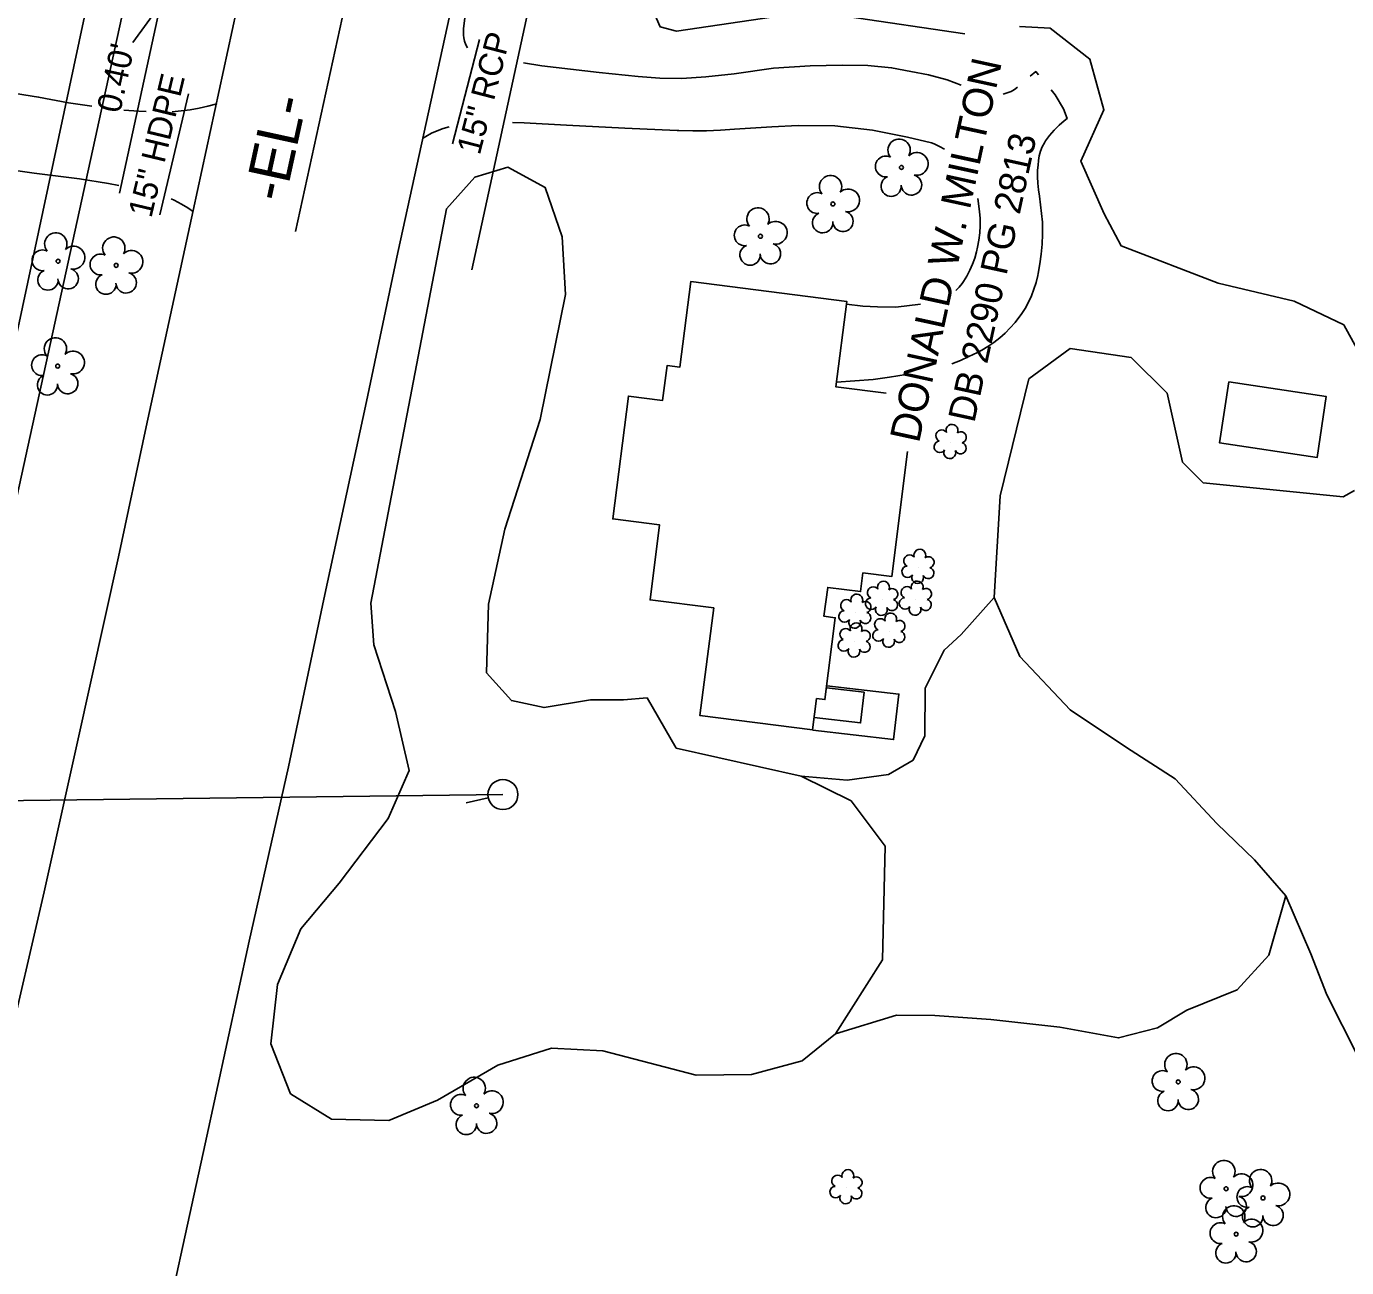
# Model space of a CAD drawing. Extents: x 1611576 to 1617186, y 899279 to 905462.
# Drawn here: x 1616512.4 to 1616732.1, y 901153.2 to 901359.7 of the extents above; entities that cross this region are included whole.
import ezdxf

# ---------------------------------------------------------------- set-up
doc = ezdxf.new("R2010")
doc.units = 0
for name, color, linetype in [('Default', 7, 'Continuous'), ('Exist Building', 7, 'Continuous'), ('Exist Horizontal Alignment', 7, 'Continuous'), ('Exist Horizontal Alignment Direction Label', 7, 'Continuous'), ('Exist Other Culture Area Outline', 7, 'Continuous'), ('Exist Property Deed Book Text', 7, 'Continuous'), ('Exist Property Line Leader', 7, 'Continuous'), ('Exist Property Line Text', 7, 'Continuous'), ('Exist Property Owner Text', 7, 'Continuous'), ('Exist Right of Way Line', 7, 'Continuous'), ('Exist Roads EOP', 7, 'Continuous'), ('Exist Roads Soil', 7, 'Continuous'), ('Exist Structure Minor Pipes HDPE 15 Inch', 7, 'Continuous'), ('Exist Structure Minor Pipes HDPE 15 Inch Text', 7, 'Continuous'), ('Exist Structure Minor Pipes RCP 15 Inch', 7, 'Continuous'), ('Exist Structure Minor Pipes RCP 15 Inch Text', 7, 'Continuous'), ('Exist Vegetation Hedge Row', 7, 'Continuous'), ('Exist Vegetation Shrub CELL', 7, 'Continuous'), ('Exist Vegetation Tree CELL', 7, 'Continuous'), ('Exist Vegetation Woods Line', 7, 'Continuous'), ('Prop 6 In Gas Line (B2)', 7, 'Continuous'), ('Prop OH Pow Lines', 7, 'Continuous'), ('Prop OH Pow Tel CATV Lines', 7, 'Continuous')]:
    doc.layers.add(name, color=color, linetype=linetype)

msp = doc.modelspace()

# ---------------------------------------------------------------- linework, layer by layer
at = {"layer": 'Default'}
msp.add_line((1616589.28, 901231.39), (1616585.62, 901230.55), dxfattribs=at)
msp.add_circle((1616591.71, 901231.94), 2.5, dxfattribs=at)
at = {"layer": 'Exist Building'}
msp.add_lwpolyline([(1616659.05, 901289.01), (1616656.41, 901268.21), (1616651.62, 901268.82), (1616651.23, 901265.71), (1616645.75, 901266.41), (1616645.13, 901261.6), (1616647.02, 901261.36), (1616645.28, 901247.73), (1616643.89, 901247.9), (1616643.23, 901242.69), (1616624.5, 901245.07), (1616626.78, 901262.99), (1616616.19, 901264.33), (1616617.78, 901276.79), (1616609.99, 901277.78), (1616612.59, 901298.23), (1616618.28, 901297.51), (1616619.02, 901303.31), (1616621.16, 901303.04), (1616622.97, 901317.27), (1616648.92, 901313.97), (1616647.11, 901299.76), (1616655.48, 901298.7)], dxfattribs=at)
msp.add_lwpolyline([(1616712.49, 901300.59), (1616728.7, 901298.15), (1616727.17, 901288), (1616710.96, 901290.44)], close=True, dxfattribs=at)
at = {"layer": 'Exist Horizontal Alignment'}
msp.add_line((1616557.22, 901325.62), (1616574.73, 901406.06), dxfattribs=at)
at = {"layer": 'Exist Other Culture Area Outline'}
for points in [[(1616645.58, 901250.04), (1616657.59, 901248.64), (1616656.71, 901241.09), (1616643.29, 901242.65)], [(1616645.54, 901249.7), (1616651.81, 901248.97), (1616651.21, 901243.87), (1616643.49, 901244.78)]]:
    msp.add_lwpolyline(points, dxfattribs=at)
at = {"layer": 'Exist Property Line Leader'}
msp.add_line((1616534.45, 901362.96), (1616530.14, 901357.04), dxfattribs=at)
at = {"layer": 'Exist Right of Way Line'}
for p, q in [((1616527.91, 901332), (1616545.42, 901412.44)), ((1616586.53, 901319.24), (1616604.05, 901399.68))]:
    msp.add_line(p, q, dxfattribs=at)
at = {"layer": 'Exist Roads EOP'}
for points in [[(1616540.19, 901329.11), (1616548.81, 901369.07), (1616557.77, 901410.37), (1616567.02, 901453.27), (1616575.93, 901495.52), (1616585.07, 901537.99), (1616593.68, 901579.55), (1616600.7, 901615.07)], [(1616637.67, 901615.79), (1616627.7, 901573.43), (1616618.84, 901530.91), (1616609.97, 901489.21), (1616601.04, 901446.38), (1616592.15, 901403.91), (1616582.89, 901361.63), (1616574.25, 901322.14)], [(1616508.56, 901186.1), (1616509, 901188.14), (1616515.39, 901215.77), (1616520.9, 901240.73), (1616527.75, 901271.5), (1616532.38, 901293.11), (1616540.19, 901329.11)], [(1616574.25, 901322.14), (1616569.01, 901297.34), (1616561.91, 901264.45), (1616556.05, 901236.56), (1616549.5, 901207.53), (1616542.18, 901173.84), (1616533.69, 901135.03)]]:
    msp.add_lwpolyline(points, dxfattribs=at)
at = {"layer": 'Exist Roads Soil'}
for points in [[(1616585.81, 901356.14), (1616585.53, 901356.68), (1616585.33, 901357.25), (1616585.19, 901357.84), (1616585.15, 901358.27), (1616585.16, 901359.39), (1616585.77, 901364.24), (1616586.93, 901371.54), (1616587.46, 901376.46), (1616587.58, 901382.96)], [(1616523.33, 901346.48), (1616519.44, 901347.01), (1616514.46, 901347.97), (1616509.21, 901348.79), (1616505.25, 901349.23), (1616499.66, 901349.68), (1616493.34, 901350.26), (1616486.34, 901351.16), (1616473.14, 901353.09), (1616460.08, 901355.19), (1616448.14, 901357.11), (1616436.59, 901359.1), (1616422.94, 901361.95)], [(1616667.94, 901349.96), (1616665.63, 901350.82), (1616662.52, 901351.67), (1616659.57, 901352.23), (1616656.37, 901352.84), (1616652.44, 901353.23), (1616648.15, 901353.29), (1616642.85, 901353.15), (1616636.73, 901352.76), (1616630.18, 901351.84), (1616625.46, 901351.32), (1616621.46, 901351.05), (1616617.81, 901351.12), (1616614.23, 901351.4), (1616607.71, 901352.04), (1616598.21, 901353.19), (1616595.11, 901353.67)], [(1616680.82, 901351.69), (1616680.36, 901352.21), (1616679.45, 901351.44)], [(1616666.38, 901303.62), (1616667.83, 901304.17), (1616669.26, 901304.79), (1616670.66, 901305.49), (1616671.37, 901305.87), (1616672.41, 901306.48), (1616673.42, 901307.16), (1616674.37, 901307.9), (1616675.28, 901308.7), (1616676.13, 901309.56), (1616676.93, 901310.47), (1616677.24, 901310.87), (1616677.94, 901311.82), (1616678.58, 901312.81), (1616679.15, 901313.84), (1616679.65, 901314.91), (1616680.07, 901316.01), (1616680.42, 901317.14), (1616680.69, 901318.28), (1616680.76, 901318.61), (1616681.06, 901320.23), (1616681.28, 901321.86), (1616681.43, 901323.5), (1616681.5, 901325.14), (1616681.49, 901326.78), (1616681.47, 901327.18), (1616680.97, 901331.49), (1616680.8, 901332.56), (1616680.69, 901333.63), (1616680.65, 901334.72), (1616680.68, 901335.8), (1616680.75, 901336.63), (1616680.81, 901337.41), (1616680.94, 901338.19), (1616681.15, 901338.95), (1616681.44, 901339.68), (1616681.8, 901340.38), (1616681.99, 901340.69), (1616682.68, 901341.6), (1616683.43, 901342.46), (1616684.24, 901343.27), (1616685.11, 901344.03), (1616685.62, 901344.42), (1616685.01, 901346.02), (1616683.61, 901348.34), (1616682.94, 901349.2)], [(1616677.32, 901349.64), (1616676.85, 901349.25), (1616676.25, 901348.91), (1616675.62, 901348.65), (1616674.96, 901348.46)], [(1616544.09, 901346.83), (1616542.63, 901346.43), (1616541.15, 901346.1), (1616539.66, 901345.84), (1616538.16, 901345.66), (1616536.66, 901345.54)], [(1616532.37, 901345.58), (1616531.12, 901345.63), (1616528.64, 901345.8)], [(1616582.79, 901343.03), (1616581.77, 901342.74), (1616580.78, 901342.38), (1616579.81, 901341.94), (1616578.88, 901341.43), (1616578.34, 901341.09)], [(1616665.19, 901339.29), (1616664.34, 901339.77), (1616663.46, 901340.18), (1616663.02, 901340.35), (1616659, 901341.29), (1616653.23, 901342.44), (1616646.92, 901343.16), (1616640.85, 901343.26), (1616636.45, 901343.04), (1616630.24, 901342.64), (1616627.93, 901342.46), (1616625.61, 901342.37), (1616623.29, 901342.36), (1616620.97, 901342.42), (1616620.73, 901342.43), (1616612, 901342.79), (1616602.3, 901343.29), (1616595.24, 901343.67), (1616593.32, 901343.74)], [(1616460.38, 901326.31), (1616464.07, 901327.91), (1616467.97, 901329.54), (1616471.15, 901330.85), (1616474.63, 901332.24), (1616478.05, 901333.56), (1616481.89, 901334.93), (1616484.93, 901335.73), (1616488.23, 901336.48), (1616491.34, 901336.98), (1616492.83, 901337.1), (1616496.3, 901337.13), (1616499.77, 901336.95), (1616503.08, 901336.62), (1616507.42, 901336.19), (1616513.71, 901335.32), (1616521.24, 901334.36), (1616526.1, 901333.58), (1616527.83, 901333.25)], [(1616536.51, 901331.02), (1616537, 901330.81), (1616538.22, 901330.15), (1616539.31, 901329.52), (1616540.21, 901328.87)], [(1616667.07, 901315.79), (1616667.62, 901316.35), (1616668.11, 901316.97), (1616668.32, 901317.28), (1616668.9, 901318.2), (1616669.42, 901319.15), (1616669.86, 901320.15), (1616670.22, 901321.17), (1616670.51, 901322.22), (1616670.68, 901323.01), (1616670.91, 901324.18), (1616671.06, 901325.36), (1616671.13, 901326.55), (1616671.12, 901327.75), (1616671.03, 901328.94), (1616670.75, 901331.12)], [(1616648.86, 901313.52), (1616651.6, 901313.19), (1616654.06, 901313.07), (1616657.1, 901313.04), (1616661.2, 901313.5)], [(1616647.21, 901300.53), (1616653.31, 901301), (1616656.05, 901301.37), (1616658.79, 901301.82)]]:
    msp.add_lwpolyline(points, dxfattribs=at)
at = {"layer": 'Exist Structure Minor Pipes HDPE 15 Inch'}
msp.add_line((1616539.41, 901348.52), (1616534.61, 901328.4), dxfattribs=at)
at = {"layer": 'Exist Structure Minor Pipes RCP 15 Inch'}
msp.add_line((1616583.3, 901340.18), (1616587.79, 901357.52), dxfattribs=at)
msp.add_line((1616583.3, 901340.18), (1616587.79, 901357.52), dxfattribs=at)
at = {"layer": 'Exist Vegetation Hedge Row'}
for points in [[(1616641.34, 901234.99), (1616648.97, 901234.35), (1616655.87, 901235.25), (1616659.97, 901237.67), (1616661.9, 901241.71), (1616661.94, 901249.63), (1616665.15, 901255.97), (1616667.98, 901258.55), (1616673.47, 901264.74)], [(1616722, 901215.09), (1616719.16, 901205.22), (1616713.86, 901199.46), (1616705.48, 901196.06), (1616700.62, 901193.14), (1616694.15, 901191.44), (1616684.38, 901193.24), (1616672.92, 901194.54), (1616663.58, 901195.17), (1616657.19, 901195.24), (1616647.03, 901192.15)]]:
    msp.add_lwpolyline(points, dxfattribs=at)
at = {"layer": 'Exist Vegetation Shrub CELL'}
for p, q in [((1616666.2, 901290.49), (1616666.2, 901290.49)), ((1616660.85, 901269.71), (1616660.85, 901269.71)), ((1616654.8, 901264.4), (1616654.8, 901264.4)), ((1616660.41, 901264.43), (1616660.41, 901264.43)), ((1616650.36, 901262.27), (1616650.36, 901262.27)), ((1616656.01, 901259.1), (1616656.01, 901259.1)), ((1616650.23, 901257.46), (1616650.23, 901257.46)), ((1616648.87, 901166.52), (1616648.87, 901166.52))]:
    msp.add_line(p, q, dxfattribs=at)
for centre, radius, start, end in [((1616664.72, 901291.62), 0.968, 35.8908, 245.4216), ((1616666.43, 901292.53), 0.99, 334.8391, 200.4717), ((1616667.87, 901291.36), 0.929, 284.4567, 126.0861), ((1616664.4, 901289.78), 0.955, 95.1099, 327.9534), ((1616667.84, 901289.56), 0.937, 204.9913, 73.4601), ((1616666.07, 901288.8), 0.984, 151.2797, 21.387), ((1616661.08, 901271.76), 0.99, 334.8391, 200.4717), ((1616659.05, 901269.01), 0.955, 95.1099, 327.9534), ((1616659.37, 901270.84), 0.968, 35.8908, 245.4216), ((1616662.49, 901268.79), 0.937, 204.9913, 73.4601), ((1616662.52, 901270.58), 0.929, 284.4567, 126.0861), ((1616660.72, 901268.03), 0.984, 151.2797, 21.387), ((1616650.59, 901264.31), 0.99, 334.8391, 200.4717), ((1616653.32, 901265.53), 0.968, 35.8908, 245.4216), ((1616655.03, 901266.44), 0.99, 334.8391, 200.4717), ((1616656.48, 901265.27), 0.929, 284.4567, 126.0861), ((1616658.93, 901265.56), 0.968, 35.8908, 245.4216), ((1616660.64, 901266.47), 0.99, 334.8391, 200.4717), ((1616662.08, 901265.3), 0.929, 284.4567, 126.0861), ((1616648.88, 901263.4), 0.968, 35.8908, 245.4216), ((1616652.03, 901263.14), 0.929, 284.4567, 126.0861), ((1616653, 901263.69), 0.955, 95.1099, 327.9534), ((1616654.68, 901262.71), 0.984, 151.2797, 21.387), ((1616656.44, 901263.47), 0.937, 204.9913, 73.4601), ((1616658.61, 901263.72), 0.955, 95.1099, 327.9534), ((1616660.28, 901262.75), 0.984, 151.2797, 21.387), ((1616662.05, 901263.5), 0.937, 204.9913, 73.4601), ((1616648.56, 901261.57), 0.955, 95.1099, 327.9534), ((1616650.23, 901260.59), 0.984, 151.2797, 21.387), ((1616652, 901261.34), 0.937, 204.9913, 73.4601), ((1616654.52, 901260.23), 0.968, 35.8908, 245.4216), ((1616656.24, 901261.14), 0.99, 334.8391, 200.4717), ((1616657.68, 901259.97), 0.929, 284.4567, 126.0861), ((1616648.75, 901258.59), 0.968, 35.8908, 245.4216), ((1616650.46, 901259.5), 0.99, 334.8391, 200.4717), ((1616651.91, 901258.33), 0.929, 284.4567, 126.0861), ((1616654.21, 901258.4), 0.955, 95.1099, 327.9534), ((1616657.64, 901258.17), 0.937, 204.9913, 73.4601), ((1616648.43, 901256.75), 0.955, 95.1099, 327.9534), ((1616651.87, 901256.53), 0.937, 204.9913, 73.4601), ((1616655.88, 901257.42), 0.984, 151.2797, 21.387), ((1616650.11, 901255.78), 0.984, 151.2797, 21.387), ((1616649.1, 901168.56), 0.99, 334.8391, 200.4717), ((1616647.07, 901165.81), 0.955, 95.1099, 327.9534), ((1616647.39, 901167.65), 0.968, 35.8908, 245.4216), ((1616650.51, 901165.59), 0.937, 204.9913, 73.4601), ((1616650.54, 901167.39), 0.929, 284.4567, 126.0861), ((1616648.74, 901164.84), 0.984, 151.2797, 21.387)]:
    msp.add_arc(centre, radius, start, end, dxfattribs=at)
at = {"layer": 'Exist Vegetation Tree CELL'}
for p, q in [((1616658.02, 901336.26), (1616658.02, 901336.26)), ((1616646.61, 901330.19), (1616646.61, 901330.19)), ((1616634.55, 901324.81), (1616634.55, 901324.81)), ((1616517.7, 901320.66), (1616517.7, 901320.66)), ((1616527.36, 901319.97), (1616527.36, 901319.97)), ((1616517.63, 901303.21), (1616517.63, 901303.21)), ((1616704.07, 901184.14), (1616704.07, 901184.14)), ((1616587.32, 901180.17), (1616587.32, 901180.17)), ((1616712.04, 901166.36), (1616712.04, 901166.36)), ((1616718.18, 901164.83), (1616718.18, 901164.83)), ((1616713.71, 901158.81), (1616713.71, 901158.81))]:
    msp.add_line(p, q, dxfattribs=at)
for centre in [(1616658.02, 901336.26), (1616646.61, 901330.19), (1616634.55, 901324.81), (1616517.7, 901320.66), (1616527.36, 901319.97), (1616517.63, 901303.21), (1616704.07, 901184.14), (1616587.32, 901180.17), (1616712.04, 901166.36), (1616718.18, 901164.83), (1616713.71, 901158.81)]:
    msp.add_circle(centre, 0.326, dxfattribs=at)
for centre, radius, start, end in [((1616657.63, 901339.14), 1.86, 330.1651, 219.7134), ((1616655.41, 901336.42), 1.73, 62.6636, 279.3457), ((1616660.57, 901336.85), 1.9, 257.1011, 134.1999), ((1616646.23, 901333.06), 1.86, 330.1651, 219.7134), ((1616656.31, 901333.14), 1.69, 111.5671, 6.231), ((1616659.69, 901333.36), 1.7, 181.2822, 74.56), ((1616644.01, 901330.34), 1.73, 62.6636, 279.3457), ((1616649.16, 901330.78), 1.9, 257.1011, 134.1999), ((1616634.16, 901327.69), 1.86, 330.1651, 219.7134), ((1616637.1, 901325.4), 1.9, 257.1011, 134.1999), ((1616644.91, 901327.07), 1.69, 111.5671, 6.231), ((1616648.28, 901327.29), 1.7, 181.2822, 74.56), ((1616517.32, 901323.53), 1.86, 330.1651, 219.7134), ((1616526.97, 901322.84), 1.86, 330.1651, 219.7134), ((1616631.94, 901324.97), 1.73, 62.6636, 279.3457), ((1616515.1, 901320.81), 1.73, 62.6636, 279.3457), ((1616520.25, 901321.25), 1.9, 257.1011, 134.1999), ((1616529.9, 901320.56), 1.9, 257.1011, 134.1999), ((1616632.84, 901321.69), 1.69, 111.5671, 6.231), ((1616636.22, 901321.91), 1.7, 181.2822, 74.56), ((1616524.75, 901320.12), 1.73, 62.6636, 279.3457), ((1616516, 901317.54), 1.69, 111.5671, 6.231), ((1616519.37, 901317.76), 1.7, 181.2822, 74.56), ((1616525.65, 901316.85), 1.69, 111.5671, 6.231), ((1616529.03, 901317.07), 1.7, 181.2822, 74.56), ((1616517.25, 901306.08), 1.86, 330.1651, 219.7134), ((1616515.02, 901303.37), 1.73, 62.6636, 279.3457), ((1616520.18, 901303.8), 1.9, 257.1011, 134.1999), ((1616515.93, 901300.09), 1.69, 111.5671, 6.231), ((1616519.3, 901300.31), 1.7, 181.2822, 74.56), ((1616703.69, 901187.01), 1.86, 330.1651, 219.7134), ((1616706.62, 901184.73), 1.9, 257.1011, 134.1999), ((1616586.94, 901183.05), 1.86, 330.1651, 219.7134), ((1616701.47, 901184.29), 1.73, 62.6636, 279.3457), ((1616584.72, 901180.33), 1.73, 62.6636, 279.3457), ((1616589.87, 901180.76), 1.9, 257.1011, 134.1999), ((1616702.37, 901181.02), 1.69, 111.5671, 6.231), ((1616705.75, 901181.24), 1.7, 181.2822, 74.56), ((1616585.62, 901177.05), 1.69, 111.5671, 6.231), ((1616589, 901177.27), 1.7, 181.2822, 74.56), ((1616711.66, 901169.23), 1.86, 330.1651, 219.7134), ((1616714.59, 901166.95), 1.9, 257.1011, 134.1999), ((1616717.79, 901167.71), 1.86, 330.1651, 219.7134), ((1616709.44, 901166.51), 1.73, 62.6636, 279.3457), ((1616715.57, 901164.99), 1.73, 62.6636, 279.3457), ((1616720.73, 901165.42), 1.9, 257.1011, 134.1999), ((1616710.34, 901163.24), 1.69, 111.5671, 6.231), ((1616713.72, 901163.46), 1.7, 181.2822, 74.56), ((1616713.32, 901161.69), 1.86, 330.1651, 219.7134), ((1616716.47, 901161.71), 1.69, 111.5671, 6.231), ((1616719.85, 901161.94), 1.7, 181.2822, 74.56), ((1616711.1, 901158.97), 1.73, 62.6636, 279.3457), ((1616716.26, 901159.4), 1.9, 257.1011, 134.1999), ((1616712, 901155.69), 1.69, 111.5671, 6.231), ((1616715.38, 901155.91), 1.7, 181.2822, 74.56)]:
    msp.add_arc(centre, radius, start, end, dxfattribs=at)
at = {"layer": 'Exist Vegetation Woods Line'}
for points in [[(1616638.29, 901361.53), (1616620.62, 901358.93), (1616617.89, 901359.63), (1616615.61, 901364.87)], [(1616668.54, 901358.5), (1616648.99, 901361.39)], [(1616735.03, 901303.91), (1616731.61, 901310.06), (1616723.38, 901314), (1616710.71, 901316.99), (1616694.57, 901323.25), (1616691.75, 901328.53), (1616687.88, 901337.3), (1616691.71, 901345.86), (1616689.35, 901354.3), (1616682.78, 901359.42), (1616677.66, 901359.72)], [(1616654.85, 901204.46), (1616647.03, 901192.15), (1616641.49, 901187.64), (1616633.08, 901185.38), (1616623.85, 901185.26), (1616608.35, 901189.31), (1616599.81, 901189.73), (1616590.89, 901186.93), (1616580.8, 901181.12), (1616572.71, 901177.74), (1616563.2, 901177.94), (1616556.38, 901182.16), (1616553.11, 901190.47), (1616554.22, 901200.34), (1616558.09, 901209.61), (1616564.44, 901217.21), (1616572.61, 901227.94), (1616576.12, 901235.95), (1616573.84, 901245.73), (1616570.23, 901256.82), (1616569.73, 901263.78), (1616582.33, 901329.36), (1616587.05, 901334.66), (1616592.53, 901336.29), (1616598.75, 901332.94), (1616601.55, 901324.7), (1616602.1, 901315.15), (1616597.91, 901294.35), (1616592.03, 901276.08), (1616589.33, 901263.62), (1616588.97, 901252.2), (1616593.12, 901247.57), (1616598.56, 901246.42), (1616606.31, 901247.7), (1616611.76, 901247.71), (1616615.69, 901248.04), (1616620.54, 901239.66), (1616641.34, 901234.99), (1616649.64, 901230.87), (1616655.32, 901223.38), (1616654.85, 901204.46)], [(1616733.95, 901188.39), (1616728.79, 901198.62), (1616726.16, 901205.44), (1616722, 901215.09), (1616716.74, 901221.06), (1616710.47, 901227.12), (1616703.56, 901234.55), (1616695.44, 901239.75), (1616686.08, 901246.04), (1616677.73, 901254.88), (1616673.47, 901264.74), (1616674.43, 901281.64), (1616679.2, 901301.07), (1616686.07, 901306.14), (1616696.22, 901304.64), (1616702.21, 901298.73), (1616704.81, 901287.22), (1616708.25, 901283.78), (1616731.51, 901281.48), (1616733.39, 901282.51)]]:
    msp.add_lwpolyline(points, dxfattribs=at)
at = {"layer": 'Prop 6 In Gas Line (B2)'}
msp.add_line((1616442.17, 900967.71), (1616564.88, 901528.63), dxfattribs=at)
at = {"layer": 'Prop OH Pow Lines'}
msp.add_line((1616496.67, 901230.74), (1616591.71, 901231.94), dxfattribs=at)
at = {"layer": 'Prop OH Pow Tel CATV Lines'}
msp.add_line((1616494.69, 901233.15), (1616522.09, 901361.37), dxfattribs=at)

# ---------------------------------------------------------------- texts
at = {"layer": 'Exist Horizontal Alignment Direction Label'}
msp.add_text('-EL-', height=7, rotation=77.7167, dxfattribs=at).set_placement((1616555.4, 901330.28))
at = {"layer": 'Exist Property Deed Book Text'}
msp.add_text('DB 2290 PG 2813', height=4.5, rotation=77.7167, dxfattribs=at).set_placement((1616670.14, 901293.65))
at = {"layer": 'Exist Property Line Text'}
msp.add_text("0.40'", height=4, rotation=77.7167, dxfattribs=at).set_placement((1616528.01, 901345.14))
at = {"layer": 'Exist Property Owner Text'}
msp.add_text('DONALD W. MILTON', height=5, rotation=77.7167, dxfattribs=at).set_placement((1616660.93, 901290.27))
at = {"layer": 'Exist Structure Minor Pipes HDPE 15 Inch Text'}
msp.add_text('15" HDPE', height=4, rotation=76.5794, dxfattribs=at).set_placement((1616533.21, 901327.73))
at = {"layer": 'Exist Structure Minor Pipes RCP 15 Inch Text'}
msp.add_text('15" RCP', height=4, rotation=75.4772, dxfattribs=at).set_placement((1616587.85, 901338.18))

doc.saveas('drawing.dxf')
